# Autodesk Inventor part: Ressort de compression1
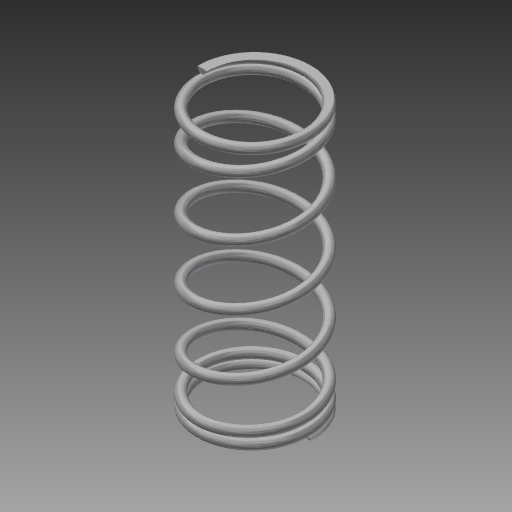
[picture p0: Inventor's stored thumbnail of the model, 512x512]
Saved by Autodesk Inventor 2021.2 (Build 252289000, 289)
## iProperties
CustomPartVersion: 1
Created: 2018-06
Part Number: Ressort de compression1
Material: Steel
Document SubType Name: Modeling
Designer: Fabian Perrée
Density: 2.18 g/cm^3
Appearance: Steel
Author: Fabian Perrée
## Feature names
1. Main Coil Feature(R)
2. Bobine de transition de départ 1 (droite)
3. Coil  Start Transition 2(R)
4. Coil  Start Transition 3(R)
5. Coil  Start Transition 4(R)
6. Bobine des extrémités de départ (droite)
7. Fonction de coupe de départ [Extrusion]
8. Bobine de transition de fin 1 (droite)
9. Bobine de transition de fin 2 (droite)
10. Bobine de transition de fin 3 (droite)
11. Bobine de transition de fin 4 (droite)
12. Bobine de fin (droite)
13. Fonction de coupe de fin (droite) [Extrusion]
14. Fonction de coupe à extrémités lisses (droite) [Extrusion]
15. Plain Ends Cut  2(R) [Extrusion]
16. Main Coil Feature(L)
17. Bobine de transition de départ 1 (gauche)
18. Bobine de transition de départ 2 (gauche)
19. Bobine de transition de départ 3 (gauche)
20. Bobine de transition de départ 4 (gauche)
21. Bobine de extrémités de départ (gauche)
22. Fonction de coupe de départ (gauche) [Extrusion]
23. Bobine de transition de fin 1 (gauche)
24. Bobine de transition de fin 2 (gauche)
25. Bobine de transition de fin 3 (gauche)
26. Bobine de transition de fin 4 (gauche)
27. Bobine de fin (gauche)
28. Fonction de coupe de fin (gauche) [Extrusion]
29. Cut Plain Ends Cut 1(L) [Extrusion]
30. Cut Plain Ends Cut 2(L) [Extrusion]
## Parameters: d0 = 0.125 mm, da_d = 0.5 mm, da_D2 = 5 mm, da_ti = 3.15544 mm, da_nz1 = 15 mm, spiral_Angle = 1.80629 mm, d2 = 3.15544 mm, d4 = 32.5 mm, d5 = 0, d6 = 90 deg, d7 = 90 deg, d8 = 0, d9 = 0, d12 = 1.62191 mm, d13 = -2.12292 mm, d14 = 0.5 mm, d15 = 0, d16 = 2.49158 mm, d18 = 2.5 mm, d19 = 0, d20 = 90 deg, d21 = 90 deg, d22 = 0, d23 = 0, d24 = 1.82772 mm, d26 = 2.5 mm, d27 = 0, d28 = 90 deg, d29 = 90 deg, d30 = 0, d31 = 0, d32 = 1.16386 mm, d34 = 2.5 mm, d35 = 0, d36 = 90 deg, d37 = 90 deg, d38 = 0, d39 = 0, d40 = 0.5 mm, d42 = 2.5 mm, d43 = 0, d44 = 90 deg, d45 = 90 deg, d46 = 0, d47 = 0, d48 = 2.49158 mm, d50 = 1.875 mm, d51 = 0, d52 = 90 deg, d53 = 90 deg, d54 = 0, d55 = 0, d56 = 1.82772 mm, d58 = 1.875 mm, d59 = 0, d60 = 90 deg, d61 = 90 deg, d62 = 0, d63 = 0, d64 = 1.16386 mm, d66 = 1.875 mm, d67 = 0, d68 = 90 deg, d69 = 90 deg, d70 = 0, d71 = 0, d72 = 0.5 mm, d74 = 1.875 mm, d75 = 0, d76 = 90 deg, d77 = 90 deg, d78 = 0, d79 = 0, End_Pitch = 0.50827 mm, d82 = 15 mm, d83 = 0, d84 = 90 deg, d85 = 90 deg, d86 = 0, d87 = 0, d88 = 0.50827 mm, d91 = 0, d92 = 90 deg, d93 = 90 deg, d94 = 0, d95 = 0, d96 = 6 mm, d97 = 0.50827 mm, d98 = 0, d99 = 6 mm, d100 = 0.50827 mm, d101 = 0, d102 = 0, d103 = 0, d104 = 0, d105 = 0, d106 = 0, d108 = 0, d112 = 0, d113 = 0, d114 = 0, const_zero = 0, Not_rightdir = 0, d121 = 0.13527 mm, d131 = 0, d132 = 0, d133 = 0, d134 = 0, d135 = 0.125 mm, d137 = 3.15544 mm, d139 = 32.5 mm, d140 = 0, d141 = 90 deg, d142 = 90 deg, d143 = 0, d144 = 0, d145 = 1.62191 mm, d146 = -2.12292 mm, d147 = 0.13527 mm, d148 = 0.0082 mm, d149 = 0.5 mm, d150 = 0, d151 = 0, d152 = 2.49158 mm, d154 = 2.5 mm, d155 = 0, d156 = 90 deg, d157 = 90 deg, d158 = 0, d159 = 0, d160 = 1.82772 mm, d162 = 2.5 mm, d163 = 0, d164 = 90 deg, d165 = 90 deg, d166 = 0, d167 = 0, d168 = 1.16386 mm, d170 = 2.5 mm, d171 = 0, d172 = 90 deg, d173 = 90 deg, d174 = 0, d175 = 0, d176 = 0.5 mm, d178 = 2.5 mm, d179 = 0, d180 = 90 deg, d181 = 90 deg, d182 = 0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
